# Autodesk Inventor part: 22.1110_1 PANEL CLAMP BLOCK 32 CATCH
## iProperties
Created: 2007-04
Part Number: 22.1110_1 PANEL CLAMP BLOCK 32 CATCH
Material: ABS Plastic
Document SubType Name: Modeling
Designer: Andy Moles
Density: 1.06 g/cm^3
Author: Andy Moles
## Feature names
1. Base1
